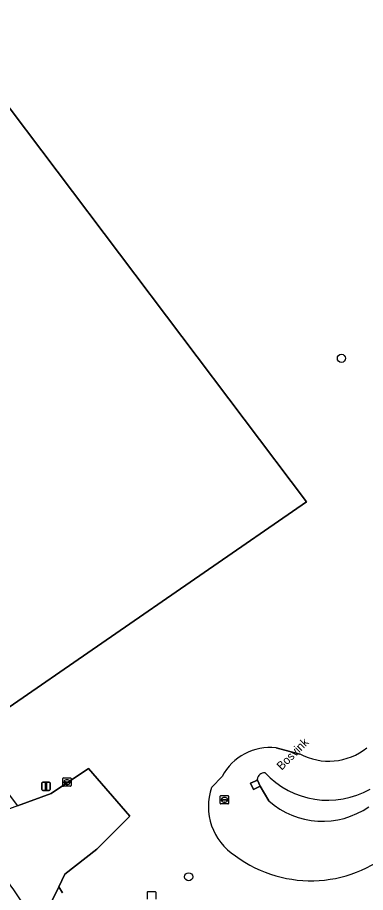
# Model space of a CAD drawing. Extents: x 156661 to 157576, y 383570 to 384425.
# Drawn here: x 157120.3 to 157162.1, y 383934.2 to 384039.3 of the extents above; entities that cross this region are included whole.
import ezdxf

# ---------------------------------------------------------------- set-up
doc = ezdxf.new("R2010")
doc.units = 0
for name, color, linetype in [('IMGEO_Boom', 7, 'Continuous'), ('IMGEO_Brandkraan', 7, 'Continuous'), ('IMGEO_Greppel_droge_sloot', 7, 'Continuous'), ('IMGEO_Groenvoorziening', 7, 'Continuous'), ('IMGEO_Kolk', 7, 'Continuous'), ('IMGEO_Lichtmast', 7, 'Continuous'), ('IMGEO_Oever', 7, 'Continuous'), ('IMGEO_Openbare_ruimte_label', 7, 'Continuous'), ('IMGEO_Rijbaan_lokaal_open', 7, 'Continuous'), ('IMGEO_Rioolput', 7, 'Continuous'), ('IMGEO_Terreindeel_gesloten', 7, 'Continuous'), ('IMGEO_Voetpad_open', 7, 'Continuous')]:
    doc.layers.add(name, color=color, linetype=linetype)

msp = doc.modelspace()

# ---------------------------------------------------------------- linework, layer by layer
at = {"layer": 'IMGEO_Boom'}
for centre in [(157159.17, 383998.4), (157140.83, 383936.14)]:
    msp.add_circle(centre, 0.489, dxfattribs=at)
at = {"layer": 'IMGEO_Brandkraan'}
for p, q in [((157135.88, 383933.43), (157135.88, 383934.28)), ((157135.95, 383934.36), (157136.8, 383934.36)), ((157136.88, 383934.28), (157136.88, 383933.43))]:
    msp.add_line(p, q, dxfattribs=at)
for points in [[(157135.88, 383933.43), (157135.88, 383934.28)], [(157135.95, 383934.36), (157136.8, 383934.36)], [(157136.88, 383934.28), (157136.88, 383933.43)]]:
    msp.add_lwpolyline(points, dxfattribs=at)
for centre, start, end in [((157135.95, 383934.28), 91.552, 178.448), ((157135.95, 383934.28), 91.552, 178.448), ((157136.8, 383934.28), 1.552, 88.448), ((157136.8, 383934.28), 1.552, 88.448)]:
    msp.add_arc(centre, 0.0765, start, end, dxfattribs=at)
at = {"layer": 'IMGEO_Greppel_droge_sloot'}
msp.add_lwpolyline([(157149.06, 383947.84), (157149.09, 383947.75), (157149.41, 383947.01), (157150.45, 383945.26)], dxfattribs=at)
for centre, radius, start, end in [((157149.96, 383947.72), 0.913, 87.0362, 172.8465), ((157157.55, 383955.59), 10.26, 222.6552, 299.6813), ((157156.91, 383952.49), 9.69, 228.1896, 305.0149)]:
    msp.add_arc(centre, radius, start, end, dxfattribs=at)
at = {"layer": 'IMGEO_Groenvoorziening'}
for points in [[(157075.19, 384135.05), (157079.98, 384129.64), (157085.94, 384121.17), (157092.14, 384111.94), (157093.57, 384107.82), (157092.75, 384099.97), (157089.93, 384085.6), (157084.35, 384074.37), (157087.62, 384070.54), (157154.96, 383981.15), (157118.08, 383955.71), (157048.49, 384046.4), (157047.52, 384049.68), (157043.53, 384046.73), (157050.31, 384037.74), (157052.87, 384034.35), (157120.28, 383944.64), (157124.33, 383946.14), (157128.8, 383949.15), (157133.77, 383943.41), (157129.81, 383939.45), (157125.96, 383936.44), (157125.24, 383934.93), (157125.69, 383934.22)], [(157151.32, 383951.62), (157154.17, 383950.88)], [(157143.6, 383946.88), (157144.87, 383948.19)]]:
    msp.add_lwpolyline(points, dxfattribs=at)
msp.add_lwpolyline([(157118.08, 383955.71), (157154.96, 383981.15), (157087.62, 384070.54), (157084.35, 384074.37), (157080.51, 384071.09), (157047.52, 384049.68), (157048.49, 384046.4)], close=True, dxfattribs=at)
for centre, radius, start, end in [((157150.62, 383945.16), 6.51, 83.8156, 152.216), ((157157.64, 383957.39), 7.37, 241.9236, 308.5702), ((157150.18, 383944.56), 6.98, 160.637, 237.6994), ((157155.51, 383950.82), 15.16, 233.2939, 314.1575)]:
    msp.add_arc(centre, radius, start, end, dxfattribs=at)
at = {"layer": 'IMGEO_Kolk'}
for p, q in [((157144.63, 383944.95), (157144.63, 383945.81)), ((157144.7, 383945.88), (157145.56, 383945.88)), ((157145.12, 383945.66), (157145.14, 383945.66)), ((157145.63, 383945.81), (157145.63, 383944.95)), ((157145.56, 383944.88), (157144.7, 383944.88)), ((157144.89, 383945.37), (157144.89, 383945.39)), ((157144.93, 383945.42), (157145.33, 383945.42)), ((157145.33, 383945.34), (157144.93, 383945.34)), ((157145.14, 383945.1), (157145.11, 383945.1)), ((157145.37, 383945.39), (157145.37, 383945.37))]:
    msp.add_line(p, q, dxfattribs=at)
for points in [[(157144.63, 383944.95), (157144.63, 383945.81)], [(157144.7, 383945.88), (157145.56, 383945.88)], [(157145.63, 383945.81), (157145.63, 383944.95)], [(157145.56, 383944.88), (157144.7, 383944.88)]]:
    msp.add_lwpolyline(points, dxfattribs=at)
for centre, radius, start, end in [((157144.71, 383945.8), 0.0765, 91.552, 178.448), ((157144.71, 383945.8), 0.0765, 91.552, 178.448), ((157145.55, 383945.8), 0.0765, 1.552, 88.448), ((157145.55, 383945.8), 0.0765, 1.552, 88.448), ((157144.71, 383944.96), 0.0765, 181.552, 268.448), ((157144.71, 383944.96), 0.0765, 181.552, 268.448), ((157144.93, 383945.38), 0.0403, 85.8775, 175.7526), ((157144.92, 383945.37), 0.0366, 178.938, 274.7102), ((157145.33, 383945.38), 0.0386, 1.7309, 96.639), ((157145.33, 383945.38), 0.043, 264.8664, 352.4533), ((157145.55, 383944.96), 0.0765, 271.552, 358.448), ((157145.55, 383944.96), 0.0765, 271.552, 358.448)]:
    msp.add_arc(centre, radius, start, end, dxfattribs=at)
for centre, major_axis, ratio, start_param, end_param in [((157145.12, 383945.38), (-0.387, 0.002), 0.722429, 4.712389, 7.853982), ((157145.14, 383945.38), (-0.39, 0.002), 0.717154, 1.570796, 4.712389)]:
    msp.add_ellipse(centre, major_axis=major_axis, ratio=ratio, start_param=start_param, end_param=end_param, dxfattribs=at)
at = {"layer": 'IMGEO_Lichtmast'}
for p, q in [((157123.22, 383946.6), (157123.22, 383947.4)), ((157123.22, 383947.4), (157123.22, 383946.6)), ((157123.32, 383947.5), (157124.11, 383947.5)), ((157124.11, 383947.5), (157123.32, 383947.5)), ((157124.21, 383947.4), (157124.21, 383946.6)), ((157124.21, 383946.6), (157124.21, 383947.4)), ((157124.11, 383946.5), (157123.32, 383946.5)), ((157123.32, 383946.5), (157124.11, 383946.5))]:
    msp.add_line(p, q, dxfattribs=at)
msp.add_lwpolyline([(157123.64, 383947.37), (157123.79, 383947.37), (157123.79, 383946.62), (157123.64, 383946.62), (157123.64, 383947.37)], dxfattribs=at)
for centre, start, end in [((157123.32, 383947.4), 90, 180), ((157123.32, 383947.4), 90, 180), ((157124.11, 383947.4), 0, 90), ((157124.11, 383947.4), 360, 90), ((157123.32, 383946.6), 180, 270), ((157123.32, 383946.6), 180, 270), ((157124.11, 383946.6), 270, 0), ((157124.11, 383946.6), 270, 0)]:
    msp.add_arc(centre, 0.1, start, end, dxfattribs=at)
at = {"layer": 'IMGEO_Oever'}
for points in [[(157154.17, 383950.88), (157151.32, 383951.62)], [(157144.87, 383948.19), (157143.6, 383946.88)], [(157150.45, 383945.26), (157149.41, 383947.01), (157148.61, 383946.63), (157148.27, 383947.37), (157149.09, 383947.75), (157149.06, 383947.84)]]:
    msp.add_lwpolyline(points, dxfattribs=at)
for centre, radius, start, end in [((157150.62, 383945.16), 6.51, 83.8156, 152.216), ((157157.64, 383957.39), 7.37, 241.9236, 308.5702), ((157149.96, 383947.72), 0.913, 87.0362, 172.8465), ((157157.55, 383955.59), 10.26, 222.6552, 299.6813), ((157150.18, 383944.56), 6.98, 160.637, 237.6994), ((157156.91, 383952.49), 9.69, 228.1896, 305.0149), ((157155.51, 383950.82), 15.16, 233.2939, 314.1575)]:
    msp.add_arc(centre, radius, start, end, dxfattribs=at)
at = {"layer": 'IMGEO_Rijbaan_lokaal_open'}
for points in [[(157128.8, 383949.15), (157124.33, 383946.14), (157120.28, 383944.64), (157118.35, 383943.92)], [(157122.87, 383929.95), (157124.19, 383932.73), (157125.24, 383934.93), (157125.96, 383936.44), (157129.81, 383939.45), (157133.77, 383943.41), (157128.8, 383949.15)]]:
    msp.add_lwpolyline(points, dxfattribs=at)
msp.add_arc((157058.3, 383890.89), 75.47, 31.1717, 36.4855, dxfattribs=at)
msp.add_arc((157058.3, 383890.89), 75.47, 31.1717, 36.4855, dxfattribs=at)
at = {"layer": 'IMGEO_Rioolput'}
for p, q in [((157125.73, 383947.08), (157125.73, 383947.93)), ((157125.8, 383948), (157126.66, 383948)), ((157126.22, 383947.78), (157126.24, 383947.78)), ((157126.73, 383947.93), (157126.73, 383947.08)), ((157126.66, 383947), (157125.8, 383947)), ((157125.99, 383947.5), (157125.99, 383947.51)), ((157126.03, 383947.55), (157126.43, 383947.55)), ((157126.42, 383947.46), (157126.03, 383947.46)), ((157126.24, 383947.22), (157126.21, 383947.22)), ((157126.47, 383947.51), (157126.47, 383947.5))]:
    msp.add_line(p, q, dxfattribs=at)
for points in [[(157125.73, 383947.08), (157125.73, 383947.93)], [(157125.8, 383948), (157126.66, 383948)], [(157126.73, 383947.93), (157126.73, 383947.08)], [(157126.66, 383947), (157125.8, 383947)]]:
    msp.add_lwpolyline(points, dxfattribs=at)
for centre, radius, start, end in [((157125.8, 383947.93), 0.0765, 91.552, 178.448), ((157125.8, 383947.93), 0.0765, 91.552, 178.448), ((157126.65, 383947.93), 0.0765, 1.552, 88.448), ((157126.65, 383947.93), 0.0765, 1.552, 88.448), ((157125.8, 383947.08), 0.0765, 181.552, 268.448), ((157125.8, 383947.08), 0.0765, 181.552, 268.448), ((157126.03, 383947.51), 0.0403, 85.8775, 175.7526), ((157126.02, 383947.5), 0.0366, 178.938, 274.7102), ((157126.43, 383947.5), 0.043, 264.8664, 352.4533), ((157126.43, 383947.51), 0.0386, 1.7309, 96.639), ((157126.65, 383947.08), 0.0765, 271.552, 358.448), ((157126.65, 383947.08), 0.0765, 271.552, 358.448)]:
    msp.add_arc(centre, radius, start, end, dxfattribs=at)
for centre, major_axis, ratio, start_param, end_param in [((157126.22, 383947.5), (-0.387, 0.002), 0.722429, 4.712389, 7.853982), ((157126.24, 383947.5), (-0.39, 0.002), 0.717154, 1.570796, 4.712389)]:
    msp.add_ellipse(centre, major_axis=major_axis, ratio=ratio, start_param=start_param, end_param=end_param, dxfattribs=at)
at = {"layer": 'IMGEO_Terreindeel_gesloten'}
msp.add_lwpolyline([(157149.09, 383947.75), (157148.27, 383947.37), (157148.61, 383946.63), (157149.41, 383947.01)], close=True, dxfattribs=at)
at = {"layer": 'IMGEO_Voetpad_open'}
msp.add_lwpolyline([(157125.69, 383934.22), (157125.24, 383934.93), (157124.19, 383932.73)], dxfattribs=at)

# ---------------------------------------------------------------- texts
at = {"layer": 'IMGEO_Openbare_ruimte_label'}
msp.add_text('Bosvink', height=1, rotation=45, dxfattribs=at).set_placement((157152, 383948.88))

doc.saveas('drawing.dxf')
